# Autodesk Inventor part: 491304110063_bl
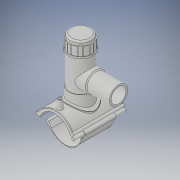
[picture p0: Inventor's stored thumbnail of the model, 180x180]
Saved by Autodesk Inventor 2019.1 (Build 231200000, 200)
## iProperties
Created: 2017-07
Part Number: 491304110063_bl
Material: Generic
Description: PLASSON TAPPING TEE SADDLE 110mm x 63mm
Document SubType Name: Modeling
Designer: KIM
Mass: 1712.7 g
Surface Area: 2671.49 cm^2
Volume: 1712.7 cm^3
Density: 1 g/cm^3
Appearance: Default
Author: KIM
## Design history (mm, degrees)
derived "491304.ipt"
feature "Solid1::491304.ipt" dims "ScaleForDerivedMember" = 10
feature "Solid2::491304.ipt" dims "ScaleForDerivedMember" = 10
feature "Solid4::491304.ipt" dims "ScaleForDerivedMember" = 10
feature "Solid5::491304.ipt" dims "ScaleForDerivedMember" = 10
tag "TaggingFeature1"
body "Solid1"
body "Solid2"
other parameters: "d1" = 101.118 [user parameter], "d2" = 249.6 [user parameter], "d3" = 27.5 [user parameter], "d4" = 176 [user parameter], "d5" = 0 [user parameter], "d6" = 0.1 [user parameter], "d8" = 0 [user parameter], "d40" = 66 [user parameter], "d41" = 97.65 [user parameter], "d43" = 0 [user parameter], "d45" = 0 [user parameter], "d47" = 156.159 [user parameter], "d79" = 15 [user parameter], "d80" = 70.4 [user parameter], "d82" = 5 deg [user parameter], "d84" = 4 [user parameter], "d85" = 14 [user parameter], "d86" = 0 [user parameter], "d87" = 3 [user parameter], "d88" = 0 [user parameter], "d97" = 3.52 [user parameter], "d98" = 0 [user parameter], "d102" = 1.1 [user parameter], "d120" = 140 deg [user parameter], "d123" = 606.708 [user parameter], "d126" = 0 [user parameter], "d153" = 176 [user parameter], "d154" = 0 [user parameter], "d159" = -1.7764 [user parameter], "d162" = 105.6 [user parameter], "d163" = 0 [user parameter], "d164" = 55 [user parameter], "d169" = 4.0905 [user parameter], "d172" = 0 [user parameter], "d173" = 1 [user parameter], "d175" = 55 [user parameter], "d176" = 20 deg [user parameter], "d177" = 7.7 [user parameter], "d180" = 0 [user parameter], "d184" = 6.16 [user parameter], "d187" = 60.5 [user parameter], "d188" = 15 [user parameter], "d189" = 7.7 [user parameter], "d190" = 0 [user parameter], "d191" = 82.5 [user parameter], "d195" = 90 deg [user parameter], "d197" = 0 [user parameter], "d199" = 0 [user parameter], "d200" = 7.7 [user parameter], "d202" = 0 [user parameter], "d203" = 195 [user parameter], "d206" = 75.6 [user parameter], "d207" = 146.25 [user parameter], "d208" = 152.1 [user parameter], "d209" = 181.35 [user parameter], "d210" = 76.86 [user parameter], "d212" = 72.45 [user parameter], "d213" = 39.15 [user parameter], "d216" = 0 [user parameter], "d217" = 11 [user parameter], "d218" = 5.5 [user parameter], "d219" = 1.1 [user parameter], "d224" = 0 [user parameter], "d259" = 50.4 [user parameter], "d260" = 63 [user parameter], "d263" = 156 [user parameter], "d265" = 0 [user parameter], "d267" = 13.00006 [user parameter], "d268" = 2.60001 [user parameter], "d269" = 2.60001 [user parameter], "d271" = 2.60001 [user parameter], "d273" = 0 [user parameter], "d274" = 23.56194 [user parameter], "d275" = 88 [user parameter], "d277" = 44 [user parameter], "d278" = 176 [user parameter], "d280" = 0 [user parameter], "d283" = 0 [user parameter], "d285" = 0 [user parameter], "d290" = 11 [user parameter], "d293" = 60.5 [user parameter], "d294" = 56.65 [user parameter], "d296" = 16.5 [user parameter], "d299" = 75 [user parameter], "d300" = 3 [user parameter], "d301" = 5 [user parameter], "d303" = 81.9 [user parameter], "d304" = 69.3 [user parameter], "d305" = 45 deg [user parameter], "d306" = 50.4 [user parameter], "d307" = 68.75 [user parameter], "d308" = 66 [user parameter], "d310" = 1 [user parameter], "B" = 156 [user parameter], "L" = 176 [user parameter], "d_t" = 6 [user parameter], "H2" = 195 [user parameter], "H1" = 75 [user parameter], "d_1" = 63 [user parameter]
